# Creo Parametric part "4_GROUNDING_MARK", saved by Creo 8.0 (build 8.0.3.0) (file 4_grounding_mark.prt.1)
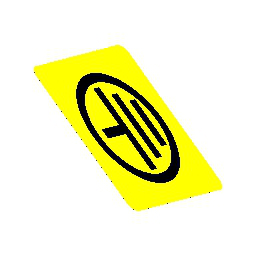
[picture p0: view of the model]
Units: Custom; MM, KILOGRAM, SECS

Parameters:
  PCODE = "Q/DKBA8.817.1004"
  PROI_REVISION = "0"
  PROI_VERSION = "2+"
  PROI_BRANCH = "main"
  PROI_RELEASE = "Final"

Other parameters: PWEIGHT, PROI_MODIFIED

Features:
  1. datum plane "SIDE"
  2. datum plane "TOP"
  3. datum plane "FRONT"
  4. coordinate system
  5. protrusion
  6. protrusion
  7. protrusion

Other named items: CSYS_PART_DEF

Layers: 0_ALL_AXIS, 0_ALL_CSYS, 0_ALL_CURVES, 0_ALL_PLANES, 0_ALL_POINTS, 0_ALL_SURFS, 0_GROUNDING_MARK

Surfaces: 24 plane, 2 cylinder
